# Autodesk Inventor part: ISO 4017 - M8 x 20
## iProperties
Comments: To add or edit properties for Autodesk Inventor files, use iProperties.
Created: 2004-08
Part Number: ISO 4017 - M8 x 20
Vendor: Autodesk Inc.
Document SubType Name: Modeling
Designer: John Blackburn
Material: Default
Description: Hex-Head Bolt
Standard: ISO 4017
Alert: To add or edit properties for Autodesk Inventor files, use iProperties.
Control State: 0
Master: False
Checked Out: False
Shininess: 64.0
Length Units: 11269
Angle Units: 11279
Time Units: 11290
Mass Units: 11283
Length Display Precision: 3
Angle Display Precision: 2
Compacted: True
EGR: 1
Density: 0.0
Volumn: 0.0
Area: 0.0
PropertySet Name: Model Information
Author: John Blackburn
Revision Number: 8
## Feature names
1. Body [Revolution]
2. Head [Extrusion]
3. Chamfer1 [Revolution]
4. Chamfer2
